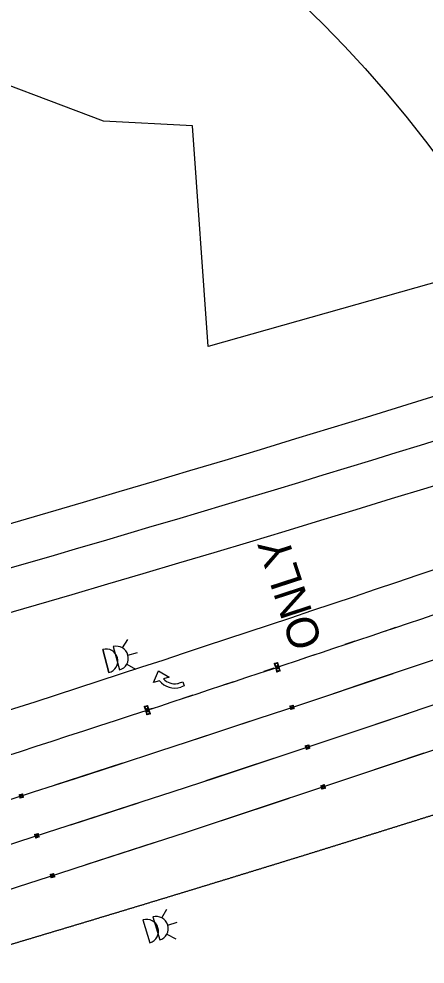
# Model space of a CAD drawing. Extents: x 2471014 to 2497726, y 6959577 to 6980268.
# Drawn here: x 2484329.2 to 2484443.3, y 6967868.8 to 6968134.6 of the extents above; entities that cross this region are included whole.
import ezdxf

# ---------------------------------------------------------------- set-up
doc = ezdxf.new("R2010")
doc.units = 0
for name, color, linetype in [('13', 7, 'Continuous'), ('18', 7, 'Continuous'), ('23', 7, 'Continuous'), ('5', 7, 'Continuous'), ('59', 7, 'Continuous'), ('C-COMM-IDEN', 7, 'Continuous'), ('Level 40', 7, 'Continuous'), ('p_structure fence', 7, 'Continuous'), ('p_structure wall', 7, 'Continuous'), ('RDWY_PAVE_XSTREET_FOC', 7, 'Continuous'), ('S-BRDG-BENT', 7, 'Continuous'), ('S-BRDG-DECK', 7, 'Continuous'), ('SHADE SW', 7, 'Continuous'), ('V7_25', 7, 'Continuous'), ('V7_50', 7, 'Continuous')]:
    doc.layers.add(name, color=color, linetype=linetype)

msp = doc.modelspace()

# ---------------------------------------------------------------- linework, layer by layer
at = {"layer": '13'}
msp.add_arc((2482515.09, 6974235.12), 6524, 284.818276, 290.670716, dxfattribs=at)
for points in [[(2484383.45, 6967891.46), (2484384.31, 6967891.73), (2484385.17, 6967891.99), (2484386.03, 6967892.25), (2484386.9, 6967892.52), (2484387.76, 6967892.78), (2484388.62, 6967893.05), (2484389.48, 6967893.31), (2484390.34, 6967893.58), (2484391.21, 6967893.84), (2484392.07, 6967894.11), (2484392.93, 6967894.37), (2484393.79, 6967894.64), (2484394.65, 6967894.9), (2484395.51, 6967895.17), (2484396.38, 6967895.43), (2484397.24, 6967895.7), (2484398.1, 6967895.96), (2484398.96, 6967896.23), (2484399.82, 6967896.49), (2484400.68, 6967896.76), (2484401.54, 6967897.03), (2484402.41, 6967897.29), (2484403.27, 6967897.56), (2484404.13, 6967897.82), (2484404.99, 6967898.09), (2484405.85, 6967898.36), (2484406.71, 6967898.62), (2484407.57, 6967898.89), (2484408.44, 6967899.16), (2484409.3, 6967899.42), (2484410.16, 6967899.69), (2484411.02, 6967899.96), (2484411.88, 6967900.22), (2484412.74, 6967900.49), (2484413.6, 6967900.76), (2484414.46, 6967901.03), (2484415.32, 6967901.29), (2484416.18, 6967901.56), (2484417.05, 6967901.83), (2484417.91, 6967902.1), (2484418.77, 6967902.36), (2484419.63, 6967902.63), (2484420.49, 6967902.9), (2484421.35, 6967903.17), (2484422.21, 6967903.44), (2484423.07, 6967903.7), (2484423.93, 6967903.97), (2484424.79, 6967904.24), (2484425.65, 6967904.51), (2484426.51, 6967904.78), (2484427.38, 6967905.05), (2484428.24, 6967905.32), (2484429.1, 6967905.58), (2484429.96, 6967905.85), (2484430.82, 6967906.12), (2484431.68, 6967906.39), (2484432.54, 6967906.66), (2484433.4, 6967906.93), (2484434.26, 6967907.2), (2484435.12, 6967907.47), (2484435.98, 6967907.74), (2484436.84, 6967908.01), (2484437.7, 6967908.28), (2484438.56, 6967908.55), (2484439.42, 6967908.82), (2484440.28, 6967909.09), (2484441.14, 6967909.36), (2484442, 6967909.63), (2484442.86, 6967909.9), (2484443.72, 6967910.17), (2484444.58, 6967910.44), (2484445.44, 6967910.71), (2484446.3, 6967910.98), (2484447.16, 6967911.25)], [(2484319.59, 6967872.17), (2484320.46, 6967872.43), (2484321.32, 6967872.69), (2484322.18, 6967872.95), (2484323.05, 6967873.2), (2484323.91, 6967873.46), (2484324.77, 6967873.72), (2484325.64, 6967873.98), (2484326.5, 6967874.23), (2484327.37, 6967874.49), (2484328.23, 6967874.75), (2484329.09, 6967875.01), (2484329.96, 6967875.27), (2484330.82, 6967875.53), (2484331.68, 6967875.78), (2484332.55, 6967876.04), (2484333.41, 6967876.3), (2484334.27, 6967876.56), (2484335.14, 6967876.82), (2484336, 6967877.08), (2484336.86, 6967877.34), (2484337.73, 6967877.6), (2484338.59, 6967877.86), (2484339.45, 6967878.11), (2484340.32, 6967878.37), (2484341.18, 6967878.63), (2484342.04, 6967878.89), (2484342.91, 6967879.15), (2484343.77, 6967879.41), (2484344.63, 6967879.67), (2484345.5, 6967879.93), (2484346.36, 6967880.19), (2484347.22, 6967880.45), (2484348.09, 6967880.71), (2484348.95, 6967880.97), (2484349.81, 6967881.23), (2484350.68, 6967881.49), (2484351.54, 6967881.75), (2484352.4, 6967882.02), (2484353.26, 6967882.28), (2484354.13, 6967882.54), (2484354.99, 6967882.8), (2484355.85, 6967883.06), (2484356.72, 6967883.32), (2484357.58, 6967883.58), (2484358.44, 6967883.84), (2484359.3, 6967884.1), (2484360.17, 6967884.37), (2484361.03, 6967884.63), (2484361.89, 6967884.89), (2484362.75, 6967885.15), (2484363.62, 6967885.41), (2484364.48, 6967885.67), (2484365.34, 6967885.94), (2484366.2, 6967886.2), (2484367.07, 6967886.46), (2484367.93, 6967886.72), (2484368.79, 6967886.99), (2484369.65, 6967887.25), (2484370.52, 6967887.51), (2484371.38, 6967887.77), (2484372.24, 6967888.04), (2484373.1, 6967888.3), (2484373.97, 6967888.56), (2484374.83, 6967888.83), (2484375.69, 6967889.09), (2484376.55, 6967889.35), (2484377.41, 6967889.61), (2484378.28, 6967889.88), (2484379.14, 6967890.14), (2484380, 6967890.41), (2484380.86, 6967890.67), (2484381.72, 6967890.93), (2484382.59, 6967891.2), (2484383.45, 6967891.46)]]:
    msp.add_spline(points, degree=3, dxfattribs=at)
at = {"layer": '18'}
for centre, radius, start, end in [((2482515.09, 6974235.12), 6500, 284.818276, 290.670716), ((2481730.69, 6975971.12), 8440, 287.024164, 289.758917)]:
    msp.add_arc(centre, radius, start, end, dxfattribs=at)
at = {"layer": '23'}
for p, q in [((2484400.91, 6967953.32), (2484401.87, 6967953.64)), ((2484401.12, 6967953.22), (2484400.91, 6967953.32)), ((2484400.91, 6967953.32), (2484401, 6967953.06)), ((2484401, 6967953.06), (2484401.23, 6967952.36)), ((2484401.33, 6967952.58), (2484401.12, 6967953.22)), ((2484402.19, 6967952.68), (2484401.23, 6967952.36)), ((2484401.23, 6967952.36), (2484401.33, 6967952.58)), ((2484401.87, 6967953.64), (2484401.76, 6967953.43)), ((2484401.76, 6967953.43), (2484401.81, 6967953.3)), ((2484401.81, 6967953.3), (2484401.98, 6967952.79)), ((2484402.19, 6967952.68), (2484401.87, 6967953.64)), ((2484401.98, 6967952.79), (2484402.19, 6967952.68)), ((2484401.32, 6967951.89), (2484402.28, 6967952.21)), ((2484401.53, 6967951.78), (2484401.32, 6967951.89)), ((2484401.32, 6967951.89), (2484401.64, 6967950.93)), ((2484401.7, 6967951.27), (2484401.53, 6967951.78)), ((2484402.6, 6967951.25), (2484401.64, 6967950.93)), ((2484401.64, 6967950.93), (2484401.75, 6967951.14)), ((2484401.75, 6967951.14), (2484401.7, 6967951.27)), ((2484402.28, 6967952.21), (2484402.18, 6967951.99)), ((2484402.18, 6967951.99), (2484402.39, 6967951.35)), ((2484402.51, 6967951.51), (2484402.28, 6967952.21)), ((2484402.39, 6967951.35), (2484402.6, 6967951.25)), ((2484402.6, 6967951.25), (2484402.51, 6967951.51)), ((2484364.39, 6967941.25), (2484365.36, 6967941.56)), ((2484364.6, 6967941.15), (2484364.39, 6967941.25)), ((2484364.39, 6967941.25), (2484364.47, 6967940.99)), ((2484364.47, 6967940.99), (2484364.71, 6967940.28)), ((2484364.81, 6967940.51), (2484364.6, 6967941.15)), ((2484365.67, 6967940.6), (2484364.71, 6967940.28)), ((2484364.71, 6967940.28), (2484364.81, 6967940.51)), ((2484364.83, 6967939.81), (2484365.8, 6967940.13)), ((2484365.04, 6967939.72), (2484364.83, 6967939.81)), ((2484364.83, 6967939.81), (2484364.92, 6967939.56)), ((2484364.92, 6967939.56), (2484365.15, 6967938.85)), ((2484365.25, 6967939.07), (2484365.04, 6967939.72)), ((2484366.11, 6967939.17), (2484365.15, 6967938.85)), ((2484365.36, 6967941.56), (2484365.24, 6967941.36)), ((2484365.24, 6967941.36), (2484365.29, 6967941.23)), ((2484365.29, 6967941.23), (2484365.45, 6967940.72)), ((2484365.67, 6967940.6), (2484365.36, 6967941.56)), ((2484365.45, 6967940.72), (2484365.67, 6967940.6)), ((2484365.8, 6967940.13), (2484365.69, 6967939.93)), ((2484365.69, 6967939.93), (2484365.73, 6967939.79)), ((2484365.73, 6967939.79), (2484365.9, 6967939.28)), ((2484366.11, 6967939.17), (2484365.8, 6967940.13)), ((2484365.9, 6967939.28), (2484366.11, 6967939.17)), ((2484405.26, 6967941.33), (2484406.22, 6967941.65)), ((2484405.47, 6967941.23), (2484405.26, 6967941.33)), ((2484405.26, 6967941.33), (2484405.35, 6967941.07)), ((2484405.35, 6967941.07), (2484405.58, 6967940.37)), ((2484405.68, 6967940.59), (2484405.47, 6967941.23)), ((2484406.54, 6967940.69), (2484405.58, 6967940.37)), ((2484405.58, 6967940.37), (2484405.68, 6967940.59)), ((2484406.22, 6967941.65), (2484406.11, 6967941.44)), ((2484406.11, 6967941.44), (2484406.16, 6967941.31)), ((2484406.16, 6967941.31), (2484406.33, 6967940.8)), ((2484406.54, 6967940.69), (2484406.22, 6967941.65)), ((2484406.33, 6967940.8), (2484406.54, 6967940.69)), ((2484365.15, 6967938.85), (2484365.25, 6967939.07)), ((2484409.63, 6967930.13), (2484410.59, 6967930.46)), ((2484409.83, 6967930.04), (2484409.63, 6967930.13)), ((2484409.63, 6967930.13), (2484409.71, 6967929.88)), ((2484409.71, 6967929.88), (2484409.95, 6967929.17)), ((2484410.05, 6967929.39), (2484409.83, 6967930.04)), ((2484410.91, 6967929.49), (2484409.95, 6967929.17)), ((2484409.95, 6967929.17), (2484410.05, 6967929.39)), ((2484410.59, 6967930.46), (2484410.48, 6967930.25)), ((2484410.48, 6967930.25), (2484410.52, 6967930.12)), ((2484410.52, 6967930.12), (2484410.69, 6967929.61)), ((2484410.91, 6967929.49), (2484410.59, 6967930.46)), ((2484410.69, 6967929.61), (2484410.91, 6967929.49)), ((2484413.99, 6967918.94), (2484414.95, 6967919.26)), ((2484414.2, 6967918.84), (2484413.99, 6967918.94)), ((2484413.99, 6967918.94), (2484414.07, 6967918.68)), ((2484414.07, 6967918.68), (2484414.31, 6967917.98)), ((2484414.41, 6967918.2), (2484414.2, 6967918.84)), ((2484415.27, 6967918.3), (2484414.31, 6967917.98)), ((2484414.31, 6967917.98), (2484414.41, 6967918.2)), ((2484414.95, 6967919.26), (2484414.84, 6967919.05)), ((2484414.84, 6967919.05), (2484414.88, 6967918.92)), ((2484414.88, 6967918.92), (2484415.05, 6967918.41)), ((2484415.27, 6967918.3), (2484414.95, 6967919.26)), ((2484415.05, 6967918.41), (2484415.27, 6967918.3)), ((2484329.25, 6967916.41), (2484330.21, 6967916.72)), ((2484329.45, 6967916.31), (2484329.25, 6967916.41)), ((2484329.25, 6967916.41), (2484329.33, 6967916.15)), ((2484329.33, 6967916.15), (2484329.56, 6967915.44)), ((2484329.66, 6967915.66), (2484329.45, 6967916.31)), ((2484330.52, 6967915.75), (2484329.56, 6967915.44)), ((2484329.56, 6967915.44), (2484329.66, 6967915.66)), ((2484330.21, 6967916.72), (2484330.1, 6967916.52)), ((2484330.1, 6967916.52), (2484330.14, 6967916.38)), ((2484330.14, 6967916.38), (2484330.31, 6967915.87)), ((2484330.52, 6967915.75), (2484330.21, 6967916.72)), ((2484330.31, 6967915.87), (2484330.52, 6967915.75)), ((2484333.61, 6967905.21), (2484334.58, 6967905.52)), ((2484333.82, 6967905.11), (2484333.61, 6967905.21)), ((2484333.61, 6967905.21), (2484333.7, 6967904.95)), ((2484333.7, 6967904.95), (2484333.92, 6967904.24)), ((2484334.03, 6967904.46), (2484333.82, 6967905.11)), ((2484334.89, 6967904.55), (2484333.92, 6967904.24)), ((2484334.58, 6967905.52), (2484334.47, 6967905.32)), ((2484334.47, 6967905.32), (2484334.51, 6967905.18)), ((2484334.51, 6967905.18), (2484334.67, 6967904.67)), ((2484334.89, 6967904.55), (2484334.58, 6967905.52)), ((2484334.67, 6967904.67), (2484334.89, 6967904.55)), ((2484333.92, 6967904.24), (2484334.03, 6967904.46)), ((2484337.98, 6967894.01), (2484338.94, 6967894.32)), ((2484338.18, 6967893.91), (2484337.98, 6967894.01)), ((2484337.98, 6967894.01), (2484338.06, 6967893.75)), ((2484338.39, 6967893.26), (2484338.18, 6967893.91)), ((2484338.94, 6967894.32), (2484338.83, 6967894.11)), ((2484338.83, 6967894.11), (2484338.87, 6967893.98)), ((2484338.87, 6967893.98), (2484339.04, 6967893.47)), ((2484339.25, 6967893.35), (2484338.94, 6967894.32)), ((2484338.06, 6967893.75), (2484338.29, 6967893.04)), ((2484339.25, 6967893.35), (2484338.29, 6967893.04)), ((2484338.29, 6967893.04), (2484338.39, 6967893.26)), ((2484339.04, 6967893.47), (2484339.25, 6967893.35))]:
    msp.add_line(p, q, dxfattribs=at)
for points in [[(2484401.12, 6967953.22), (2484401.76, 6967953.43), (2484401.98, 6967952.79), (2484401.33, 6967952.58)], [(2484402.39, 6967951.35), (2484401.75, 6967951.14), (2484401.53, 6967951.78), (2484402.18, 6967951.99)], [(2484364.6, 6967941.15), (2484365.24, 6967941.36), (2484365.45, 6967940.72), (2484364.81, 6967940.51)], [(2484365.04, 6967939.72), (2484365.69, 6967939.93), (2484365.9, 6967939.28), (2484365.25, 6967939.07)], [(2484405.47, 6967941.23), (2484406.11, 6967941.44), (2484406.33, 6967940.8), (2484405.68, 6967940.59)], [(2484409.83, 6967930.04), (2484410.48, 6967930.25), (2484410.69, 6967929.61), (2484410.05, 6967929.39)], [(2484414.2, 6967918.84), (2484414.84, 6967919.05), (2484415.05, 6967918.41), (2484414.41, 6967918.2)], [(2484329.45, 6967916.31), (2484330.1, 6967916.52), (2484330.31, 6967915.87), (2484329.66, 6967915.66)], [(2484333.82, 6967905.11), (2484334.47, 6967905.32), (2484334.67, 6967904.67), (2484334.03, 6967904.46)], [(2484338.18, 6967893.91), (2484338.83, 6967894.11), (2484339.04, 6967893.47), (2484338.39, 6967893.26)]]:
    msp.add_lwpolyline(points, close=True, dxfattribs=at)
at = {"layer": '5'}
for centre, radius, start, end in [((2479474.04, 6969335.88), 8460, 6.37617, 6.37617), ((2481730.69, 6975971.12), 8452, 286.128593, 288.162281)]:
    msp.add_arc(centre, radius, start, end, dxfattribs=at)
at = {"layer": '59'}
msp.add_arc((2481730.69, 6975971.12), 8452, 288.162281, 289.758917, dxfattribs=at)
at = {"layer": 'C-COMM-IDEN'}
for p, q in [((2484355.69, 6967958.07), (2484357.42, 6967951.55)), ((2484358.25, 6967957.73), (2484359.76, 6967960.1)), ((2484354.47, 6967950.76), (2484352.74, 6967957.29)), ((2484352.74, 6967957.29), (2484354.47, 6967950.76)), ((2484359.82, 6967955.67), (2484362.54, 6967956.39)), ((2484359.47, 6967953.11), (2484361.93, 6967951.73))]:
    msp.add_line(p, q, dxfattribs=at)
for centre in [(2484356.56, 6967954.81), (2484353.6, 6967954.03)]:
    msp.add_arc(centre, 3.37, 284.8324, 104.8324, dxfattribs=at)
at = {"layer": 'Level 40'}
for p, q in [((2484434.97, 6967963.42), (2484432.12, 6967962.46)), ((2484423.59, 6967959.59), (2484420.75, 6967958.64)), ((2484412.22, 6967955.78), (2484409.37, 6967954.83)), ((2484400.83, 6967951.98), (2484397.99, 6967951.03)), ((2484389.45, 6967948.19), (2484386.6, 6967947.25)), ((2484378.05, 6967944.43), (2484375.2, 6967943.49)), ((2484366.65, 6967940.68), (2484365.26, 6967940.22))]:
    msp.add_line(p, q, dxfattribs=at)
at = {"layer": 'p_structure wall'}
for p, q in [((2484367.01, 6967947.94), (2484368.39, 6967951.27)), ((2484368.39, 6967951.27), (2484371.42, 6967949.52)), ((2484368.64, 6967948.49), (2484367.01, 6967947.94)), ((2484371.42, 6967949.52), (2484369.83, 6967948.99)), ((2484374.31, 6967947.85), (2484375.24, 6967948.16)), ((2484375.24, 6967948.16), (2484375.63, 6967947)), ((2484375.63, 6967947), (2484374.7, 6967946.68))]:
    msp.add_line(p, q, dxfattribs=at)
for radius, start, end in [(5.49, 218.2696, 288.559), (4.26, 222.9452, 280.6878), (4.26, 280.6878, 282.9352), (4.26, 282.9352, 288.518)]:
    msp.add_arc((2484372.95, 6967951.89), radius, start, end, dxfattribs=at)
at = {"layer": 'RDWY_PAVE_XSTREET_FOC'}
for p, q in [((2484415.38, 6967944.18), (2484434.34, 6967950.55)), ((2484419.75, 6967932.99), (2484438.71, 6967939.36)), ((2484377.42, 6967931.59), (2484396.41, 6967937.86)), ((2484381.79, 6967920.39), (2484400.77, 6967926.67)), ((2484424.11, 6967921.79), (2484443.07, 6967928.16)), ((2484339.4, 6967919.17), (2484358.42, 6967925.35)), ((2484386.15, 6967909.19), (2484405.14, 6967915.47)), ((2484343.76, 6967907.97), (2484362.78, 6967914.16)), ((2484348.13, 6967896.77), (2484367.14, 6967902.96))]:
    msp.add_line(p, q, dxfattribs=at)
at = {"layer": 'S-BRDG-BENT'}
msp.add_arc((2481980.08, 6976008.2), 8516, 284.374936, 288.450981, dxfattribs=at)
msp.add_arc((2481980.08, 6976008.2), 8516, 284.374936, 288.450981, dxfattribs=at)
at = {"layer": 'S-BRDG-DECK'}
msp.add_arc((2482515.09, 6974235.12), 6512, 284.818276, 288.849401, dxfattribs=at)
at = {"layer": 'SHADE SW'}
for p, q in [((2484369.37, 6967881.79), (2484370.79, 6967884.22)), ((2484364.05, 6967881.26), (2484366, 6967874.79)), ((2484366.8, 6967882.05), (2484368.74, 6967875.59)), ((2484371, 6967879.79), (2484373.69, 6967880.6)), ((2484370.74, 6967877.22), (2484373.24, 6967875.92))]:
    msp.add_line(p, q, dxfattribs=at)
for centre in [(2484365.02, 6967878.03), (2484367.77, 6967878.82)]:
    msp.add_arc(centre, 3.37, 286.7334, 106.7334, dxfattribs=at)
at = {"layer": 'V7_25'}
for radius in [8464, 8464, 8476, 8476, 8488, 8488]:
    msp.add_arc((2481730.69, 6975971.12), radius, 284.37496, 289.758917, dxfattribs=at)
at = {"layer": 'V7_50'}
msp.add_lwpolyline([(2484627.27, 6968111.75), (2484382.38, 6968042.48), (2484378, 6968104.47), (2484352.91, 6968105.84), (2484310.24, 6968121.89), (2484301.91, 6968121.75), (2484275.28, 6968105.36), (2484272.16, 6968082.72), (2484264.98, 6968082.51), (2484247.99, 6968074.2), (2484231.21, 6968049.34), (2483902.58, 6967954.49), (2483719.31, 6967900.88), (2483476.09, 6967843.05), (2483126.15, 6967836.92)], dxfattribs=at)
msp.add_ellipse((2484308.07, 6967658.79), major_axis=(23.18, -533), ratio=0.5, dxfattribs=at)

# ---------------------------------------------------------------- texts
at = {"layer": 'p_structure fence'}
msp.add_text('ONLY', height=8.898, rotation=108.0586, dxfattribs=at).set_placement((2484414.54, 6967959.02))

doc.saveas('drawing.dxf')
